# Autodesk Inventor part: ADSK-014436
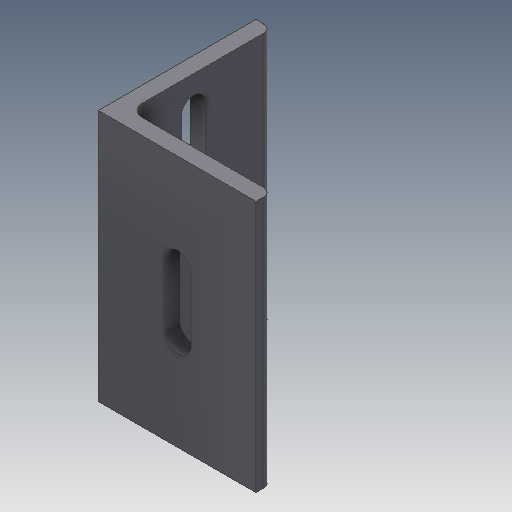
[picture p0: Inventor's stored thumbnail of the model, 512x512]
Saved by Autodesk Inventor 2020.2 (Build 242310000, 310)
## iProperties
Created: 2019-12
Part Number: ADSK-014436
Material: 1.0501 C35
Document SubType Name: Modeling
Designer: lutzd
Mass: 579.429 g
Surface Area: 265.432 cm^2
Volume: 73.9067 cm^3
Density: 7.84 g/cm^3
Appearance: Stahl
VLDS_Profile: Default Part
VLDS_TimeStamp: 2016-07-29
VLDS_FailCnt: 0
VLDS_AcceptCnt: 0
Dimensions: 63,5x101,6x63,5 mm
Mass: 0,579 kg
DocNumber: ADSK-014436
Folder: 01 - Themengebiete\Simplification\01 - Packaging machine\Parts\
VDS_Category: 3D Komponenten
VDS_NumSchm: Autodesk
VLT_Material: 1.0501 C35
Title: profile
Author: lutzd
Revision Number: -
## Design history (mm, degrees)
derived "ADSK-011643.ipt"
feature "Solide1::ADSK-011643.ipt" dims "d0" = 10
tag "Bezeichnung1"
node "Volumenkörper1"
